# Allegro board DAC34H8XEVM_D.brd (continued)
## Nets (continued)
N27118781: C265.2 C268.1 L33.1 R23.1 R100.2 R107.1
N27125590: C274.2 C277.1 L38.1 R31.1 R101.2 R109.1
N27129848: C283.2 C286.1 L42.1 R39.1 R102.2 R111.1
N27288441: R79.2 U3.2(D4)
N27288443: C95.1 J14.2(D-) U3.16(USBDM)
N27288450: C92.1 C93.1 FB14.1 U3.20(VCC)
N27288471: R80.2 U3.9(D5)
N27288510: R81.2 U3.10(D6)
N27288614: C97.1 U3.17(3V3OUT)
N27288630: C96.1 J14.3(D+) U3.15(USBDP)
N27288689: R75.1 U4.8(A1) U9.2(1A)
N27288797: R75.2 U3.1(D0)
N27288876: R76.2 U3.5(D1)
N27289021: R77.2 U3.3(D2)
N27289053: R82.2 U3.6(D7)
N27299600: R78.1 U5.9(A2)
N27358249: R16.1 T1.4(SECONDARY_DOT) T8.6(PRIMARY_DOT)
N27358251: R13.2 R16.2
N27379986: R42.1 T4.4(SECONDARY_DOT) T11.6(PRIMARY_DOT)
N27396936: R4.1 T1.6(SECONDARY) T8.4(PRIMARY)
N27404153: R36.1 T4.6(SECONDARY) T11.4(PRIMARY)
N27685853: R7.2 R99.1
N27688076: R22.2 R100.1
N27690605: R30.2 R101.1
N27692844: R38.2 R102.1
N27760065: C76.1 C77.1 C78.1 C79.1 C80.1 C81.1 FB9.2 U2.26(VCC_OUT#26) U2.29(VCC_OUT#29) U2.32(VCC_OUT#32)
N27760104: C65.1 C66.1 FB5.2 U2.47(VCC_IN_PRI)
N27760106: C64.2 U2.38(REG_CAP2)
N27760178: C180.1 FB25.2 JP7.1
N27760241: C177.1 R95.1 U17.5(OUT)
N27760265: C53.1 J9.1(CENTER) R49.2
N27760429: C75.2 U2.4(REG_CAP1)
N27760435: JP4.3(PIN3) R51.2 R103.2
N27760437: C86.1 C87.1 FB12.2 U2.8(VCC_OUT#8)
N27760441: JP5.2(PIN2) U2.31(REF_SEL)
N27760496: C82.1 C83.1 FB10.2 U2.21(VCC_OUT#21)
N27760516: C73.1 C74.1 FB8.2 U2.1(VCC_IN_SEC)
N27760568: R61.2 R65.1 R116.1 R129.2 U2.9(U3P)
N27760578: C177.2 R166.2 R167.2 U2.3(SEC REF+)
N27760635: R164.2 R165.1 TP14.1(TP) U16.8(EN) U17.1(REF)
N27760767: R60.2 R64.1 R117.1 R130.1 U2.10(U3N)
N27760883: R55.2 U2.30(TESTOUTA)
N27760967: C52.2 R48.2
N27760969: JP6.2(PIN2) U2.12(P\W\R\D\W\N\)
N27760997: C67.1 C68.1 FB6.2 U2.5(VCC1_PLL)
N27761158: C88.1 C89.1 FB13.1 U2.18(VCC_OUT#18)
N27761194: D1.1(ANODE) R52.2
N27761235: R52.1 U2.37(PLL_LOCK)
N27761514: R54.2 U2.6(U4P)
N27761516: R58.2 U2.7(U4N)
N27761629: C63.2 U2.48(VBB)
N27761758: C84.1 C85.1 FB11.2 U2.11(VCC_OUT#11)
N27792689: C1.2 R122.2 R149.2
N27792693: C2.2 R123.2 R152.2
N27795123: C4.2 R125.2 R155.2
N27795145: C3.2 R124.2 R154.2
N27836250: J18.1 JP10.1(PIN1) TP12.1(TP)
N27836254: D2.1(ANODE) R143.1
N27959634: C165.1 FB31.1 L25.2 R148.2 U11.4(FB1)
N27964126: L25.1 U11.6(SW1)
N27965290: R148.1 R151.2 U11.5(DEF_1)
N27972790: C166.1 C167.1 FB30.1 L26.2 R150.2
N27972794: C166.2 R150.1 R153.2 U11.1(ADJ2)
N28017911: C162.1 U12.5(NR/FB)
N28017929: C145.1 C164.1 R147.1 U12.4(OUT)
N28017933: C163.1 R146.2 U12.1(EN) U12.2(IN)
N28058738: C133.1 C169.1 C234.1 FB31.3 R126.2 R145.2 R146.1 U13.1(IN) U13.3(EN)
N29123763: R9.1 T1.5(SECONDARY_CT)
N29143306: R12.1 T2.5(SECONDARY_CT)
N29165572: R14.1 T3.5(SECONDARY_CT)
N29179841: R18.1 T4.5(SECONDARY_CT)
N29448574: R36.2 R40.1
N29464199: R20.2 R24.1
N29945616: R133.2 U1.D12(PLLLF)
N30016149: C240.1 R126.1 U22.1(IN) U22.3(EN)
N30175128: C146.1 C244.1 C245.1 FB34.1 R128.2 R257.2 U13.5(OUT)
N30185572: C149.1 C246.1 C247.1 R127.1 R221.2 U22.5(OUT)
N30679143: C138.1 JP11.2 JP11.4 R134.1 R135.2 U20.5(NR/FB)
N30742942: JP11.1 R137.2
N30744213: JP11.3 R136.2
N30812023: R76.1 U4.9(A2) U9.12(4A)
N30837851: R85.1 U4.5(B1)
N30839067: R138.1 U4.4(B2)
N30879489: R139.1 U5.5(B1)
N30880109: R140.1 U5.4(B2)
N30892277: R84.1 U9.3(1Y)
N30900342: R74.2 R80.1 U9.5(2A)
N30908653: R86.1 U9.6(2Y)
N30910378: R79.1 R83.2 U9.13(4O\E\) U10.1(OE)
N30914286: R82.1 U9.8(3Y)
N30924628: JP13.2 R87.2 U10.2(A)
N30955591: R81.1 U10.4(Y)
N30963273: R73.2 R77.1 U5.8(A1)
N30997791: JP9.2 R84.2
N30998469: JP12.2 R86.2
N31553936: R87.1 U9.11(4Y)
N32018373: JP8.2 U9.9(3A)
N33970284: R221.1 R315.2 U22.4(NR/FB)
N33977043: R257.1 R316.2 U13.4(NR/FB)
N34116776: C116.1 U15.6(NR)
N34116835: R168.2 R170.1 U15.3(FB/SNS)
N34123238: FB35.1 R127.2 R128.1
N34173216: R105.2 T8.1(SECONDARY_DOT)
N34173251: R104.2 T8.3(SECONDARY)
N34173344: C254.2 C259.1 L30.1 R10.1 R99.2 R105.1
N34173621: R107.2 T9.1(SECONDARY_DOT)
N34173656: R106.2 T9.3(SECONDARY)
N34174309: R109.2 T10.1(SECONDARY_DOT)
N34174344: R108.2 T10.3(SECONDARY)
N34174546: R111.2 T11.1(SECONDARY_DOT)
N34174581: R110.2 T11.3(SECONDARY)
N34195362: R131.1 U6.19(S1)
N34195366: C100.2 R206.1 U6.3(IN)
N34195397: C54.2 R70.1 R206.2 R207.1
N34195475: C99.2 R207.2 U6.4(/IN)
N34209596: J20.1(CENTER) R122.1
N34209604: J21.1(CENTER) R123.1
N34210478: J22.1(CENTER) R124.1
N34210481: J23.1(CENTER) R125.1
N34222239: J10.1(CENTER) R121.1
N34226368: J11.1(CENTER) R120.1
N34231598: J12.1(CENTER) R129.1
N34231946: J15.1(CENTER) R130.2
N34233040: J19.1(CENTER) U2.14(S\Y\N\C\)
N34259421: C252.2 C256.1 L27.1 L28.2
N34259427: C256.2 C257.1 L29.1 L30.2
N34269055: C260.2 C264.1 L31.1 L32.2
N34269061: C264.2 C267.1 L33.2 L34.1
N34269953: C270.2 C273.1 L35.2 L36.1
N34269959: C273.2 C276.1 L37.1 L38.2
N34270526: C279.2 C282.1 L39.2 L40.1
N34270532: C282.2 C285.1 L41.1 L42.2
N34315833: F3.1 JP10.2(PIN2) Q3.1(D1) Q3.2(D2) Q3.5(D5) Q3.6(D6) Q3.8(D8) U21.5(VIN)
N34315835: C152.1 C153.1 F3.2 FB20.2 Q3.4(S4) Q3.7(S7)
N34320644: Q3.3(G3) U21.4(GATE)
N34334652: J13.177 R157.1
N34334661: J13.175 R156.1
N277617093: R95.2 U16.5(OUT)
N279448106: L26.1 U11.10(SW2)

Pads without a net: J13 5 6 7 8 9 10 11 12 13 14 15 16 17 18 19 20 21 22 23 24 25 26 27 28 30 32 34 36 37 38 39 40 41 42 43 44 45 46 47 48 49 50 51 52 53 54 55 56 57 58 59 60 61 62 63 64 169 171; J14 4; NOREF#3 1; NOREF#8 1; NOREF#22 1; NOREF#27 1; NOREF#28 1; NOREF#29 1; T1 2; T2 2; T3 2; T4 2; T8 2 5; T9 2 5; T10 2 5; T11 2 5; U2 13 27 28 33; U3 8 12 13 14 22 23 24 27 28; U6 9 10 12 21 22; U21 1 3

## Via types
v1: diameter 0.914, hole 0.254, TOP to BOTTOM, 4 vias
v2: diameter 0.508, hole 0.254, TOP to BOTTOM, 1708 vias
v3: diameter 0.762, hole 0.381, TOP to BOTTOM, 72 vias
v4: diameter 0.61, hole 0.33, TOP to BOTTOM, 9 vias
v5: diameter 0.61, hole 0.305, TOP to BOTTOM, 17 vias

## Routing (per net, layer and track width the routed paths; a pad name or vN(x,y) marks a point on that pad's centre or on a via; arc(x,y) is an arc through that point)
+1.2VCLK: length 46.8
  TOP w0.508: 76.05,25.15 75.92,25.15 75.92,24.54 C238.1
  TOP w0.762: 76.05,25.27 v2(76.68,24.64) ; 76.05,25.27 76.05,25.15 ; 76.05,25.27 76.05,25.4 C242.1 ; 76.05,25.27 75.92,25.15 ; 76.05,25.27 76.43,25.65 ; 76.05,25.27 v2(77.19,25.27) ; v2(76.68,24.64) v2(77.57,24.64) ; v2(76.68,24.64) 76.68,21.42 ; v2(76.68,24.64) 76.43,24.38 C238.1 76.07,22.96 C148.1 ; 77.32,26.92 TP19.1 76.43,28.45 v2(77.95,26.92) ; 77.32,26.92 v2(77.95,26.92) ; 77.32,26.92 v2(77.19,26.92) ; 76.68,21.42 FB35.2 ; 76.68,21.42 76.17,21.93 C148.1 ; FB35.2 77.57,21.3 ; FB35.2 v2(77.19,25.27) ; 76.43,26.04 76.43,25.65 ; 76.43,26.04 C242.1 ; 76.43,26.04 v2(76.43,26.29) 76.56,26.29 v2(77.19,26.92) ; 76.43,25.65 v2(76.43,25.53) ; C242.1 75.92,27.79 ; C148.1 76.17,23.24 v2(77.57,24.64) ; v2(77.57,24.64) 77.57,24.89 v2(77.95,25.27) ; v2(77.57,24.64) 77.57,21.3 ; 77.57,21.3 77.95,21.68 v2(77.95,25.27) ; v2(77.19,26.92) 77.19,26.52 ; v2(77.95,25.27) v2(77.95,26.04) v2(77.95,26.92) ; v2(77.19,25.27) v2(77.19,26.04)
  TOP w1.524: v2(77.19,26.04) 77.19,26.52 75.79,27.91 TP19.1
  BOTTOM w0.152: U1.C12 49.04,71.04 C38.1
  BOTTOM w0.508: v2(58.76,64.53) C40.1 v2(57.79,65.53)
+1.2VD: length 37.3
  TOP w0.305: C25.1 v2(40.61,60.43) ; C36.1 v2(39.57,60.05) ; C32.1 v2(39.55,59.28)
  TOP w0.508: 55.85,31.42 55.58,31.14 54.94,31.14 v2(54.71,31.37) C233.1
  TOP w1.016: 57.38,31.75 FB30.3 C134.1 55.85,31.24 v2(55.85,31.75) ; 57.38,31.75 56.74,32.38 ; 57.38,31.75 v2(55.85,31.75) ; 52.68,31.5 v2(51.92,30.73) ; 52.68,31.5 v2(51.92,31.5) ; 52.68,31.5 v2(52.81,31.5) ; v2(51.92,30.73) 51.03,30.73 TP15.1 50.65,32.38 v2(51.92,32.38) ; v2(51.92,30.73) v2(51.92,31.5) ; 56.74,32.38 57.76,32.38 58.5,31.65 ; 56.74,32.38 55.17,32.38 ; v2(52.81,31.5) v2(53.82,31.5) 54.58,31.5 v2(54.71,31.37) ; v2(52.81,31.5) v2(52.81,32.38) ; v2(55.85,31.75) 55.45,31.75 55.17,32.03 55.17,32.38 ; v2(52.81,32.38) v2(51.92,32.38) ; v2(52.81,32.38) 55.17,32.38 ; v2(51.92,32.38) v2(51.92,31.5)
  TOP w1.524: TP15.1 51.66,31.75 v2(51.92,31.5)
  L3_PWR w0.254: U1.D7 U1.E7
  L3_PWR w0.305: U1.F5 43.34,68.55 43.69,68.2 ; U1.E5 43.34,69.41 43.64,69.11
  BOTTOM w0.127: C26.1 43.41,68.64 U1.F5 ; C31.1 43.45,66.24 U1.J5
  BOTTOM w0.254: U1.D7 U1.E7
  BOTTOM w0.305: v2(46.28,60.93) C33.1 v2(46.69,60.53) C28.1 ; C29.1 v2(39.14,63.35) ; C27.1 v2(39.57,61.72)
  BOTTOM w0.508: v2(44.45,52.78) 44.45,53.66 C30.1 44.45,53.84 v2(44.45,54.71)
  vias: v2(57,30.73)
+1.2VDAC: length 36.8
  TOP w0.508: v2(66.9,23.62) v2(67.67,23.62) ; v2(66.9,23.62) 66.4,23.11 C243.1 ; v2(66.9,23.62) 66.9,23.16 ; v2(67.67,23.62) 68.05,23.24 ; v2(67.67,23.62) 67.92,23.62 v2(68.43,24.13) v2(68.43,23.24) ; v2(67.92,22.1) 67.51,22.5 66.4,22.5 ; v2(67.92,22.1) v2(67.16,22.1) ; v2(67.92,22.1) 67.92,22.61 ; v2(67.16,22.1) 66.52,22.1 66.4,22.22 ; v2(67.16,22.1) 66.78,21.72 C170.1 66.4,21.87 66.4,22.22 ; 66.4,22.22 66.4,22.5 ; FB34.2 68.69,19.41 67.77,19.41 66.98,20.19 ; C243.1 v2(66.9,22.86) ; C243.1 66.4,22.5 ; v2(66.9,22.86) 66.9,23.16 ; v2(66.9,22.86) v2(67.67,22.86) 67.92,22.61 ; v2(68.43,23.24) 67.92,22.73 67.92,22.61 ; v2(68.43,23.24) 68.05,23.24 ; 66.9,23.16 66.98,23.24 68.05,23.24
  TOP w1.016: v2(68.43,23.24) 68.43,20.92 ; 68.43,20.92 69.15,20.19 ; 68.43,20.92 67.92,21.42 v2(67.92,22.1) ; C170.1 66.65,21.62 C147.1 ; 67.74,20.19 67.16,20.78 v2(67.16,22.1)
  TOP w1.27: C147.1 69.15,20.19 FB34.2
  TOP w1.524: 68.11,23.81 66.78,25.15 TP18.1 66.01,24.51 v2(66.9,23.62)
  BOTTOM w0.127: C20.1 46.46,69.44 U1.E9 ; C19.1 46.54,64.56 U1.L9 ; U1.K9 46.46,65.44 C13.1 ; C18.1 46.54,70.31 U1.D9 ; C23.1 47.25,68.64 U1.F10
  BOTTOM w0.152: U1.G10 47.25,67.84 C21.1 ; C14.1 47.25,67.04 U1.H10
  BOTTOM w0.305: v2(50.93,61.59) 50.9,61.62 C15.1 ; v2(50.04,61.26) 49.76,61.54 C16.1
  BOTTOM w0.508: v2(49.59,57.37) C24.1 v2(50.52,56.36)
+3.3V_LOGIC: length 15.7
  BOTTOM w0.254: U5.6 102.47,119.88 v2(102.11,120.24) ; v2(95.45,120.27) 95.71,120.01 U4.6
  BOTTOM w0.508: C139.1 v2(95.58,120.95) ; C141.1 v2(102.21,120.95)
  BOTTOM w1.016: 82.88,126.37 v2(83.9,127.38) ; 82.88,126.37 83.79,126.37 v2(83.9,126.26) ; 82.88,126.37 FB24.2 ; 82.88,126.37 82.88,126.26 v2(83.9,125.25) ; v2(82.93,124.28) 82.64,124.57 82.64,124.96 ; v2(83.82,124.28) 83.15,124.96 82.64,124.96 ; 82.64,124.96 v2(81.99,124.31) ; 82.64,124.96 FB24.2 ; 82.64,127.8 82.64,128.03 v2(82.98,128.37) ; 82.64,127.8 v2(82.04,128.4) ; 82.64,127.8 83.3,127.8 v2(83.87,128.37) ; 82.64,127.8 FB24.2
+3.3VA: length 22.1
  TOP w0.508: v2(65.38,4.57) R147.2 v2(66.27,5.33) ; v2(55.98,8.26) 55.98,7.87 56.36,7.49 ; 56.36,7.49 56.74,7.87 v2(56.74,8.26) ; 56.36,7.49 R145.1
  L6_PWR w0.127: U1.E11 U1.D10
  BOTTOM w0.102: U1.L10 47.34,64.55 C7.1
  BOTTOM w0.127: U1.D10 47.34,70.33 C8.1
  BOTTOM w0.152: C12.1 48.2,68.64 U1.F11 ; U1.J11 48.25,66.24 C10.1 ; C9.1 48.2,69.44 U1.E11
  BOTTOM w0.305: C6.1 v2(51.54,67.84) ; C11.1 v2(51.54,67.03) ; C5.1 v2(51.56,64.64)
  BOTTOM w0.508: v2(50.71,52.39) C22.1 v2(49.76,53.39)
  BOTTOM w1.016: 59.44,68.55 59.92,68.55 v2(60.05,68.68) ; 59.44,68.55 v2(60.07,67.92) ; 59.44,68.55 FB1.2 ; FB22.1 48.64,42.86 48.64,41.97 ; FB22.1 48.32,44.7 ; FB22.1 49.4,43.18 ; v2(49.53,42.55) 49.4,42.67 49.4,43.18 ; 48.32,44.7 v2(49.53,44.7) ; 48.32,44.7 48.32,44.77 ; FB1.2 59.41,67.95 v2(59.44,67.92) ; FB1.2 58.88,68.55 v2(58.78,68.66) ; FB1.2 v2(58.78,67.92) ; v2(48.64,41.28) 48.64,41.97 ; 48.64,41.97 49.53,41.97 v2(49.53,41.78) ; v2(48.64,45.09) 48.32,44.77 ; 48.32,44.77 48.07,44.77 v2(47.75,45.09) ; v2(49.53,43.31) 49.4,43.18 ; 49.4,43.18 49.4,43.94 v2(49.53,44.07)
  vias: v2(47.75,41.28)
+3.3VCLK: length 77.3
  TOP w0.305: U2.15 v2(61.21,108.68) 61.21,108.32 v2(60.93,108.05) C127.1 ; U6.1 v2(49.59,96.8) ; 23.04,105.16 23.04,105 22.94,104.9 21.54,104.9 21.37,105.07 U15.1 ; v2(49.65,97.99) 49.34,97.99 U6.2 ; v2(48.23,99.55) 48.23,99.31 48.23,99.31 48.23,99 U6.5 ; U15.2 22.55,105.72 23.04,105.23
  TOP w0.508: C179.1 v2(61.67,136.02) ; R63.1 v2(63.07,104.53) ; 24.1,105.16 R170.2 23.04,105.16 23.04,105.23 ; 24.1,105.16 24.1,105.74 24.46,105.74 24.69,105.51 ; 24.1,105.16 24.33,105.16 C215.1 ; R62.1 v2(66.12,104.54) ; v2(28.02,104.01) 28.02,103.63 ; v2(28.02,104.01) 28.4,104.39 ; v2(28.02,104.01) v2(25.73,104.01) ; 28.02,103.63 v2(28.4,103.25) ; 28.02,103.63 27.38,103.63 ; 24.85,104.89 24.69,104.89 24.57,105 23.04,105 ; 24.85,104.89 26,104.89 v2(26.11,104.78) ; 24.85,104.89 24.85,104.72 25.57,104.01 v2(25.73,104.01) ; 24.85,104.89 v2(25.73,104.01) ; 26.11,105.11 27.96,105.11 28.02,105.16 ; 26.11,105.11 v2(26.11,104.78) ; 26.11,105.11 C118.1 ; 26.11,104.39 v2(25.73,104.01) ; 26.11,104.39 28.4,104.39 ; 26.11,104.39 v2(26.11,104.78) ; v2(25.73,104.01) 25.73,103.89 25.98,103.63 25.98,103.56 ; v2(25.73,104.01) 25.73,105.13 C118.1 ; R68.1 v2(61.93,104.54) ; 28.4,104.39 v2(28.4,104.78) ; 28.4,104.39 v2(28.4,103.25) ; v2(26.11,104.78) v2(26.87,104.78) v2(27.64,104.78) v2(28.4,104.78) ; C118.1 26.85,105.51 v2(26.87,105.54) 27.41,105.54 ; C118.1 26.34,105.74 27.41,105.74 27.41,105.54 ; 28.02,105.16 v2(28.4,104.78) ; 28.02,105.16 v2(27.64,105.54) 27.41,105.54 ; v2(28.4,103.25) 27.38,103.25 ; v2(28.4,103.25) 28.4,103.12 27.31,102.04 26.64,102.04 25.98,102.69 25.98,103.56 ; 27.38,103.25 TP17.1 26.06,103.56 ; 27.38,103.25 27.38,103.63 ; R60.1 v2(53.21,106.43) ; 26.06,103.56 26.14,103.63 27.38,103.63 ; 26.06,103.56 25.98,103.56 ; R51.1 v2(61.52,132.92) ; R166.1 52.92,116.35 v2(52.91,116.33) ; v2(58.88,104.51) 58.88,104.51 R69.1 ; R53.1 52.34,114.72 v2(52.34,115.28) ; R57.1 v2(52.86,111.63) ; R47.1 v2(67.77,130.05) ; R91.1 v2(42.52,94.41) ; R61.1 v2(53.21,110.49) ; R89.1 v2(44.67,92.26)
  TOP w1.016: C215.1 24.69,105.51 C118.1
  BOTTOM w0.305: C104.1 50.36,97.99 v2(49.65,97.99)
  BOTTOM w0.508: FB12.1 55.88,111.73 v2(55.75,111.86) ; FB11.1 v2(56.29,109.6) ; v2(56.03,115.82) 56.03,115.57 FB8.1 ; FB13.2 v2(62.83,105.91) ; FB7.1 v2(69.7,116.28) ; FB4.1 v2(65.33,120.14) ; FB3.1 v2(61.98,120.19) ; v2(55.7,113.82) 55.91,113.61 FB6.1 ; C128.1 v2(59.72,107.65) ; FB5.1 v2(58.97,120.23) ; v2(70.28,109.88) FB9.1 v2(69.75,109.32) ; C103.1 v2(48.15,100.19) ; v2(50.18,96.87) C102.1 ; FB15.2 v2(47.35,92.7) ; FB10.1 v2(65.41,106.45)
  BOTTOM w1.016: v2(76.07,124.33) 76.49,124.75 77.38,124.75 ; 77.38,127.93 v2(77.85,128.4) ; 77.38,127.93 77.38,127.98 v2(76.96,128.4) ; 77.38,127.93 76.54,127.93 v2(76.07,128.4) ; 77.38,127.93 FB24.1 ; v2(77.85,124.33) 77.43,124.75 77.38,124.75 ; FB24.1 77.38,124.75 ; FB24.1 77.17,126.37 ; 77.38,124.75 v2(76.96,124.33) ; v2(76.07,126.37) 77.17,126.37 ; 77.17,126.37 77.17,126.42 v2(76.07,127.51)
  vias: v2(76.07,125.35)
+3.3VD: length 14.4
  L3_PWR w0.305: 43.56,70.48 43.34,70.26 U1.D5
  L6_PWR w0.305: U1.L5 43.34,64.59 43.61,64.31
  BOTTOM w0.127: U1.L6 44.15,64.63 C43.1 ; C45.1 43.34,70.29 U1.D5 ; C44.1 43.34,64.56 U1.L5 ; U1.H5 43.45,67.04 C41.1 ; U1.G5 43.43,67.84 C42.1 ; C46.1 44.14,70.3 U1.D6
  BOTTOM w1.016: v2(42.55,45.21) 43.05,44.7 ; 43.05,44.7 43.05,43.38 42.88,43.38 ; 43.05,44.7 42.16,44.7 v2(41.91,44.96) ; 43.05,44.7 v2(43.56,45.21) ; v2(41.91,41.53) 42.47,42.09 42.88,42.09 ; 42.88,42.09 42.88,43.38 ; 42.88,42.09 42.88,41.61 v2(42.55,41.28) ; 42.88,42.09 v2(43.69,41.28) ; 42.88,43.38 41.99,43.38 ; 42.88,43.38 v2(41.91,42.42) ; 41.99,43.38 v2(41.91,43.31) 42.04,43.18 FB22.2 ; 41.99,43.38 41.99,43.99 v2(41.91,44.07)
+5V_USB: length 29.7
  TOP w0.508: J14.1 v2(113.67,118.14) 113.67,118.08 112.95,117.37 112.95,113.79 114.73,112.01 114.73,107.7 v2(116.28,106.15) 116.28,104.93 v2(116.33,104.88)
  BOTTOM w0.508: FB14.2 111.53,115.09 C91.1 112.95,118.14 v2(113.67,118.14) ; v2(116.28,106.15) U20.2 112.78,106.15 C136.1 C137.1 U20.1 v2(116.33,104.88)
GNDA: length 257.6
  TOP w0.254: v2(60.81,115.04) 60.66,115.18 U2.2 ; v2(71.22,6.48) U13.2 v2(69.82,6.48) ; U22.2 v2(79.22,6.35) ; C78.2 v2(69.65,112.29)
  TOP w0.305: C69.2 v2(69.65,115.34) ; R98.2 v2(52.93,70.54) ; U6.13 v2(44.2,96.33) ; C70.2 v2(69.65,114.58) ; U6.8 46.86,97.66 v4(46.88,97.66) ; C57.2 64.8,119.46 v2(64.67,119.58) ; R94.2 v2(52.83,66.75) ; C73.2 v2(56.68,116.09) ; v4(47.96,96.58) 47.96,96.57 U6.23 ; C127.2 v2(60.93,106.53) ; U6.18 46.3,94.25 46.74,94.69 46.74,95.36 v4(46.88,95.51) 47.8,94.59 U6.20 ; v2(20.13,106.75) 20.41,107.02 U15.4 21.37,107.02 v2(21.67,107.31) ; v2(40.56,59.74) 40.64,59.82 C25.2 ; v2(66.5,116.28) 66.48,116.27 U2.36 ; v2(56.29,112.39) 56.46,112.39 C86.2 ; v2(69.65,113.67) 69.64,113.67 C77.2 ; C58.2 62.39,119.29 v2(62.66,119.56) ; C56.2 63.22,119.51 v2(63.3,119.58) ; R33.2 v2(52.93,64.34) ; R41.2 v2(52.88,64.92) ; v2(44.27,98.11) 44.89,97.52 45.8,96.6 v4(45.8,96.58) 44.88,97.5 U6.11 ; v2(62.2,16.13) v2(62.2,16.89) U12.6 v2(62.2,17.65) ; C32.2 v2(38.18,59.28) ; U11.11 U11.8 v2(57.51,20.45) ; v2(69.65,110.64) 69.63,110.62 C76.2 ; C65.2 59.6,119.45 v2(59.77,119.61) ; U6.24 49.23,96 v2(49.86,95.38) ; R35.2 v2(52.07,62.51) ; v2(56.29,114.27) 56.51,114.05 C67.2 ; R112.2 v2(52.1,72.36) ; C82.2 v2(64.08,106.96) ; v5(62.45,114.46) 62.71,114.71 U2.43 ; R96.2 v2(52.83,69.95) ; C84.2 56.68,110.55 v2(56.41,110.82) ; C88.2 v2(62.15,106.68) ; R97.2 v2(52.83,68.12) ; C36.2 v2(38.13,60.05) ; U6.7 v2(45.71,99.52)
  TOP w0.381: v2(48.36,21.21) U21.2 v2(48.36,19.18)
  TOP w0.508: C238.2 v2(73.89,24.38) ; v2(6.96,107.82) C143.2 v2(7.85,107.04) ; v2(75.79,62.61) TP33.1 v2(77.11,62.61) ; C258.2 v2(63.75,47.24) ; R316.1 v2(73.81,4.95) ; C134.2 56.24,28.83 56.74,28.83 ; C134.2 56.16,28.96 56.49,29.29 58.06,29.29 FB30.2 ; C134.2 v2(55.22,28.96) ; C164.2 v2(62.08,5.33) ; C161.2 v2(48.11,25.65) ; v2(77.09,93.22) TP31.1 v2(75.79,93.22) ; R50.2 v2(67.77,129.03) ; C170.2 v2(64.36,21.72) ; R21.1 v2(75.97,58.04) ; C182.2 v2(51.05,133.96) ; R39.2 v2(75.97,89.66) ; C251.1 v2(63.75,44.2) ; C242.2 v2(74.4,25.53) ; v2(85.47,130.3) 85.51,130.26 SW1.1 v2(85.51,126.45) ; v2(13.03,107.04) C144.2 v2(13.92,107.8) ; v2(46.25,91.65) C90.2 ; v2(97.03,72.87) T3.1 v2(98.22,73.79) ; v2(97.03,92.76) T4.3 v2(98.27,91.82) ; C284.2 v2(63.75,90.68) ; R55.1 v2(72.19,112.96) ; R56.2 51.32,114.73 v2(51.32,115.34) ; C257.2 v2(69.85,47.24) ; FB30.2 v2(59.41,29.21) ; FB30.2 57.76,29.21 57.38,28.83 56.74,28.83 ; C63.1 v2(57.86,120.19) ; R71.2 v2(61.93,102.46) ; v2(58.88,102.48) 58.88,102.99 58.88,103 R72.2 ; C286.2 v2(71.88,90.68) ; R153.1 v2(53.44,30.23) ; C165.2 v2(55.47,17.14) ; C266.2 v2(63.75,60.07) ; v2(77.11,72.26) TP28.1 v2(75.79,72.26) ; v2(75.79,54.48) TP34.1 v2(77.11,54.48) ; C253.1 v2(71.88,44.2) ; R131.2 v2(50.06,92.72) ; J14.5 v2(113.49,121.34) ; C279.1 69.85,87.63 ; D2.2 v2(40.87,29.21) ; C149.2 v2(77.57,9.53) ; v2(62.2,12.07) U12.3 v2(62.2,9.02) ; C234.2 v2(54.97,7.11) ; R6.1 v2(75.95,45.21) ; C268.2 v2(71.88,60.07) ; v2(85.51,125.18) SW1.2 85.51,121.45 v2(85.47,121.41) ; C261.1 v2(63.75,57.02) ; SW2.1 v2(106.74,126.73) ; R151.1 v2(55.47,18.29) ; v2(106.74,125.26) SW2.2 v2(106.74,121.53) ; v2(22.68,108.2) R168.1 v2(23.19,108.71) ; C116.2 v2(16.21,107.98) ; C252.1 v2(69.85,44.2) ; v2(52.68,7.11) FB31.2 v2(50.14,7.11) ; v2(75.79,41.66) TP29.1 v2(77.11,41.66) ; R29.1 v2(75.97,75.82) ; C275.2 v2(63.75,77.85) ; R64.2 v2(52.2,106.43) ; R65.2 52.2,110.49 v2(52.17,110.52) ; v2(51.32,111.06) 51.32,111.61 R59.2 ; C259.2 v2(71.88,47.24) ; C269.1 v2(63.75,74.8) ; C178.2 v2(52.07,133.91) ; v2(98.32,60.96) T2.3 v2(97.16,61.87) ; v2(50.85,119.79) C75.1 v2(49.99,119.02) ; C169.2 v2(68.55,7.37) ; v2(20.4,101.09) C135.2 v2(19.63,101.98) ; v2(47.4,123.55) U17.4 v2(46.09,122.49) ; v2(75.79,49.78) TP30.1 v2(77.11,49.78) ; C215.2 v2(24.59,108.2) ; R31.2 v2(75.97,76.84) ; R167.1 v2(52.96,117.36) ; C250.2 v2(99.85,109.73) ; 56.74,28.83 v2(56.74,28.19) ; J14.8 v2(113.67,115.29) ; R10.2 v2(75.97,46.23) ; R315.1 v2(81.94,4.67) ; R66.2 v2(66.12,102.48) ; C245.2 v2(69.06,12.45) ; v2(19.25,103.25) 19.28,103.23 C117.2 v2(19.89,102.62) ; C262.1 v2(71.88,57.02) ; R90.2 v2(43.93,90.84) ; R49.1 v2(67.77,133.1) ; C118.2 v2(26.11,107.7) ; C278.1 v2(63.75,87.63) ; C233.2 v2(54.71,29.21) ; v2(77.11,80.39) TP27.1 v2(75.79,80.39) ; v2(98.32,43.18) T1.1 v2(97.16,42.24) ; C111.2 v2(49.63,24.89) ; C276.2 v2(69.85,77.85) ; C162.2 v2(66.78,11.56) ; C267.2 v2(69.85,60.07) ; R67.2 v2(63.07,102.51) ; R103.1 v2(61.67,133.93) ; C247.2 v2(78.59,12.19) ; R23.2 v2(75.95,59.05) ; C148.2 v2(73.38,22.86) ; C280.1 v2(71.88,87.63) ; C147.2 v2(63.86,20.19) ; D1.2 v2(68.63,123.22) ; C270.1 v2(69.85,74.8) ; C244.2 v2(68.55,11.3) ; C180.2 v2(55.14,137.9) ; C145.2 v2(63.6,4.57) ; C277.2 v2(71.88,77.85) ; C237.2 v2(51.79,24.13) ; v2(75.77,85.09) TP32.1 v2(77.11,85.09) ; C240.2 v2(76.68,7.37) ; C181.2 v2(56.15,134.2) ; R164.1 v2(49.02,135.99) ; J14.9 v2(122.31,115.29) ; 90.81,116.31 v2(91.36,116.31) ; J14.7 v2(113.67,124.19) ; C146.2 v2(68.05,9.78) ; C246.2 v2(78.08,11.05) ; R92.2 v2(41.08,93.69) ; v2(64.87,22.86) C243.2 ; C179.2 v2(61.65,135) ; C112.2 v2(50.77,24.13) ; v2(41.9,95.99) C101.2 ; C167.2 v2(50.77,27.05) ; C133.2 v2(53.57,8.13) ; C285.2 v2(69.85,90.68) ; C64.1 v2(66.62,123.39) ; R37.1 v2(75.97,88.65) ; C163.2 v2(60.17,3.3) ; J14.6 v2(122.31,124.19) ; C260.1 v2(69.85,57.02) ; C50.2 v2(109.22,119.53) ; C271.1 v2(71.88,74.8)
  L2_GND w0.305: 96.27,44.02 96.27,43.69 96.01,43.43
  BOTTOM w0.127: U1.M9 46.54,63.91 C19.2 ; C46.2 44.14,70.92 U1.C6 ; C14.2 46.63,67.04 U1.H9 ; U1.G9 46.63,67.84 C21.2 ; U1.J6 44.08,66.24 C31.2 ; U1.K8 45.84,65.44 C13.2 ; U1.E8 45.84,69.44 C20.2 ; C43.2 44.14,63.93 U1.M6 ; U1.C9 46.54,70.96 C18.2 ; C44.2 43.34,63.91 U1.M5 ; U1.J9 46.63,66.24 C17.2 ; U1.F9 46.63,68.64 C23.2 ; C8.2 47.34,70.95 U1.C10 ; U1.H6 44.08,67.04 C41.2 ; U1.G6 44.05,67.84 C42.2 ; C26.2 44.06,68.64 U1.F6
  BOTTOM w0.152: J13.113 7.52,70.53 7.52,70.51 ; C45.2 43.34,70.94 U1.C5 ; J13.120 11.2,69.03 11.2,69.04 ; C5.2 50.57,64.64 U1.L14 ; C12.2 48.82,68.64 U1.F12 ; 13.26,62.51 13.29,62.54 J13.126 ; J13.143 7.29,58.04 7.26,58.06 ; 6.86,78.03 6.86,78.04 J13.83 ; C38.2 49.66,71.04 U1.C13 ; J13.155 7.25,55.03 7.24,55.04 ; 13.06,73.48 13.11,73.54 J13.102 ; J13.84 13.37,78.04 13.36,78.03 ; 7.26,62.48 7.32,62.54 J13.125 ; J13.156 12.71,55.03 12.65,55.09 ; J13.101 6.5,73.54 6.5,73.58 ; J13.138 12.73,59.54 12.52,59.33 ; J13.95 6.55,75.04 6.55,75.01 ; C10.2 48.88,66.24 U1.J12 ; U1.M10 47.35,63.84 C7.2 ; C6.2 U1.G14 ; 12.8,50.57 12.84,50.53 J13.174 ; 12.67,53.19 13.02,53.53 J13.162 ; 12.04,56.54 12.04,56.54 J13.150 ; 12.83,79.58 12.87,79.54 J13.78 ; U1.P13 49.75,62.24 C16.2 ; C11.2 U1.H14 ; J13.96 13.34,75.04 13.34,75.03 ; C9.2 48.83,69.44 U1.E12 ; 12.73,72.39 12.75,72.36 ; 12.75,72.36 12.78,72.34 12.78,70.74 12.98,70.53 J13.114 ; 12.75,72.36 12.75,72.19 12.9,72.03 J13.108 ; 7.19,61.11 7.26,61.04 J13.131 ; J13.137 7.24,59.54 7.21,59.51 ; 12.83,60.96 12.91,61.04 J13.132 ; 7.49,72.06 7.49,72.03 J13.107 ; 12.8,81.03 12.82,81.04 J13.72 ; 7.37,53.49 7.39,53.52 7.57,53.52 7.58,53.53 J13.161 ; 6.35,76.45 6.35,76.54 J13.89 ; J13.168 13.37,52.03 13.34,51.99 ; J13.77 7.44,79.54 7.44,79.53 ; 7.39,81.03 7.39,81.04 J13.71 ; J13.144 12.11,58.04 12.09,58.01 ; J13.149 7.28,56.54 7.24,56.49 ; 13.36,76.53 13.37,76.54 J13.90
  BOTTOM w0.254: v2(95.4,117.48) 95.71,117.78 U4.2 ; v2(103.2,117.42) 102.87,117.76 U5.1 ; U5.3 v2(101.67,118.04) ; U4.3 v2(94.91,117.97) ; U5.2 v2(102.47,117.33)
  BOTTOM w0.305: U3.26 v2(97.1,106.53) ; C54.1 51.66,98.34 v2(51.66,98.16) ; U3.25 v2(97.75,106.54) ; C33.2 46.28,59.66 v2(46.43,59.51) ; U3.21 v2(100.35,106.58) ; C28.2 v2(47.09,59.49) ; C27.2 v2(38.23,61.72) ; C29.2 v2(37.74,63.35) ; U3.18 v2(102.3,106.57)
  BOTTOM w0.381: v2(99.06,128.09) 99.09,128.09 99.42,128.43 U9.1 ; U3.7 v2(99.7,111.08) ; U9.10 v2(102.02,124.88) ; U9.4 v2(101.37,127.97) ; U9.7 v2(103.32,127.93)
  BOTTOM w0.508: C71.2 65.51,112.9 v2(65.1,113.31) ; v5(61.43,112.42) 61.18,112.17 v2(60.81,112.17) C87.2 ; v2(52.32,124.97) U16.4 v2(51.59,124.1) ; v2(59.87,106.48) 60.27,106.07 C128.2 60.48,106.07 v2(60.93,106.53) ; C68.2 v2(60.81,113.72) ; v2(61.33,64.55) C40.2 v2(62.28,65.53) ; R45.2 v2(48.67,54.38) ; C153.2 v2(40.74,26.8) ; C62.2 42.41,97.03 v2(42.98,97.03) ; v2(116.31,107.42) U20.3 113.69,107.42 113.21,106.93 112.55,106.93 R134.2 v2(112.52,107.44) ; v5(62.45,111.41) 62.69,111.17 C89.2 ; v2(112.17,112.5) C93.2 v2(111.14,111.49) ; C80.2 65.68,111.53 v2(65.1,112.12) ; v2(70.51,118.08) 70.49,118.06 C72.2 ; C136.2 v2(111.02,105.89) ; C22.2 v2(49.76,48.84) ; v2(65.13,110.79) 65.46,110.46 C79.2 C81.2 ; v2(60.81,115.04) 60.83,115.01 v2(60.83,114.58) ; v2(60.81,115.04) 60.83,115.06 C66.2 ; v2(60.81,115.04) 60.76,114.99 C74.2 ; C94.2 v2(97.61,120.95) ; v2(62.23,115.11) 62.13,115.21 C61.2 ; R18.2 v2(88.75,88.24) ; C59.2 63.65,115.44 v2(63.65,115.09) ; C85.2 v2(60.74,110.72) v5(61.43,111.41) ; C92.2 v2(110.11,110.77) ; C98.2 v2(92.96,128.37) ; C34.2 v2(53.04,77.11) ; C104.2 v2(52.09,97.2) ; C137.2 v2(111,104.88) ; v2(47.96,53.75) C30.2 v2(46.93,52.74) ; v2(65.07,115.06) 65.53,115.52 C60.2 ; C35.2 v2(52.48,76.58) ; C154.2 v2(46.1,22.1) C155.2 v2(46.58,21.59) ; v2(51.52,54.8) C24.2 v2(50.52,53.77) ; C91.2 v2(110.01,116.71) ; C83.2 64.21,111.14 v5(64.48,111.41) ; C95.2 v2(109.98,118.75) ; C152.2 v2(38.33,29.46) ; C96.2 v2(109.96,120.02) ; U10.3 v2(94.19,124.59) ; C97.2 v2(98.68,116.51) ; C141.2 v2(101.19,120.93) ; C102.2 v2(51.28,95.17) ; R14.2 v2(88.85,75.29) ; R12.2 v2(88.9,57.43) ; C140.2 v2(104.32,120.93) ; R9.2 v2(89.1,44.73) ; C139.2 v2(94.56,120.95) ; C142.2 v2(95.86,124.05) ; C103.2 v2(46.74,100.89) ; C47.2 v2(87.17,125.3)
  vias: v2(1.02,99.7) v2(1.02,95.89) v2(1.02,92.08) v2(1.02,88.27) v2(1.02,84.45) v2(1.02,80.64) v2(1.02,76.84) v2(1.02,73.03) v2(1.02,69.22) v2(1.02,65.41) v2(1.02,61.59) v2(1.02,57.79) v2(1.02,53.98) v2(1.02,50.16) v2(1.02,46.36) v2(1.09,102.18) v2(5.72,111.12) v2(5.72,107.31) v2(7.11,38.23) v2(7.87,109.86) v2(8.76,66.04) v2(10.16,107.95) v2(10.77,105.56) v2(10.77,101.35) v2(10.77,46.81) v2(10.8,104.65) v2(10.8,103.89) v2(10.8,100.38) v2(10.8,99.38) v2(10.8,98.5) v2(10.8,94.03) v2(10.8,93.03) v2(10.8,92.08) v2(10.8,91.01) v2(10.8,88.7) v2(10.8,87.76) v2(10.8,86.84) v2(10.8,85.6) v2(10.8,84.65) v2(10.8,83.74) v2(10.8,81.15) v2(10.8,78.87) v2(10.8,77.34) v2(10.8,75.06) v2(10.8,73.53) v2(10.8,72.01) v2(10.8,67.75) v2(10.8,66.83) v2(10.8,65.56) v2(10.8,64.64) v2(10.8,61.42) v2(10.8,60.07) v2(10.8,57.4) v2(10.8,54.99) v2(10.8,54.1) v2(10.8,53.09) v2(10.8,52.07) v2(10.8,51.18) v2(10.8,48.69) v2(10.8,47.75) v2(10.8,37.47) v2(11.18,89.94) v2(12.19,47.24) v2(12.42,85.8) v2(12.7,114.94) v2(12.7,87.63) v2(13.46,42.93) v2(13.97,47.12) v2(14.61,46.36) v2(14.61,37.47) v2(14.68,87.68) v2(15.24,110.49) v2(15.6,101.83) v2(15.75,46.99) v2(15.82,85.73) v2(16.13,89.38) v2(16.64,42.93) v2(16.89,45.97) v2(17.78,114.94) v2(17.78,111.76) v2(17.78,97.79) v2(17.78,92.71) v2(18.06,89.43) v2(18.42,37.47) v2(19.13,106.75) v2(19.13,105.34) v2(19.35,90.83) v2(19.63,106.05) v2(19.91,88.39) v2(20.13,105.34) v2(20.32,110.49) v2(20.96,92.41) v2(21.03,98.47) v2(21.01,89.46) v2(22.23,114.94) v2(22.17,103.25) v2(22.23,37.47) v2(22.3,93.83) v2(22.86,97.79) v2(22.78,90.86) v2(23.06,88.57) v2(23.95,94.97) v2(23.98,92.05) v2(24.94,90.4) v2(25.25,93.8) v2(25.25,88.24) v2(25.55,96.57) v2(26.04,114.94) v2(26.04,37.47) v2(26.72,95.28) v2(26.7,92.18) v2(26.82,89.84) v2(27.2,98.2) v2(27.31,88.34) v2(27.94,110.49) v2(28.65,94.16) v2(28.65,91.64) v2(28.68,97.21) v2(28.96,40.39) v2(29.31,99.24) v2(29.62,88.27) v2(29.85,139.06) v2(29.85,134.62) v2(29.85,130.81) v2(29.85,127) v2(29.85,123.19) v2(29.85,119.38) v2(29.85,114.94) v2(29.85,37.47) v2(29.85,34.29) v2(29.85,30.48) v2(29.85,26.67) v2(29.85,22.86) v2(29.85,18.41) v2(29.85,13.34) v2(29.85,10.16) v2(29.85,6.35) v2(29.85,2.54) v2(30.3,95.76) v2(30.35,93.32) v2(30.48,113.03) v2(30.48,105.41) v2(30.78,44.27) v2(31.04,97.51) v2(31.6,99.21) v2(31.65,88.34) v2(32.16,95.12) v2(33.02,130.81) v2(33.02,120.65) v2(33.05,87.63) v2(33.02,16.51) v2(33.02,11.43) v2(33.35,96.93) v2(33.91,20.7) v2(34.11,44.2) v2(34.29,0.64) v2(34.44,97.54) v2(34.93,139.06) v2(35.1,87.4) v2(35.56,105.41) v2(35.56,41.91) v2(35.56,36.83) v2(35.56,31.75) v2(35.56,6.35) v2(36.25,96.88) v2(36.53,86.03) v2(36.83,134.62) v2(36.83,2.87) v2(37.26,89.43) v2(37.44,97.64) v2(37.39,87.43) v2(37.62,117.88) v2(37.69,116.03) v2(37.69,110.26) v2(37.85,125.63) v2(37.85,123.9) v2(37.82,108.41) v2(37.92,102.77) v2(38.05,84.4) v2(38.1,120.65) v2(38.1,113.03) v2(38.1,95.1) v2(38.1,44.45) v2(38.1,39.37) v2(38.1,34.29) v2(38.2,100.89) v2(38.38,104.75) v2(38.43,90.83) v2(38.46,47.09) v2(38.73,139.06) v2(38.73,98.04) v2(38.73,6.35) v2(38.73,0.64) v2(38.91,99.16) v2(38.96,88.47) v2(38.94,86.39) v2(38.96,26.67) v2(39.04,116.15) v2(39.24,122.68) v2(39.27,117.73) v2(39.29,110.64) v2(39.37,89.66) v2(39.45,108.64) v2(39.47,82.96) v2(39.62,130.63) v2(39.6,124.69) v2(39.62,106.78) v2(39.7,129.24) v2(39.7,126.92) v2(39.75,96.52) v2(40.11,101.22) v2(40.13,87.38) v2(40.51,103.05) v2(40.67,107.82) v2(40.64,36.83) v2(40.72,100.03) v2(40.77,81.66) v2(40.84,121.08) v2(40.89,115.57) v2(40.89,88.39) v2(40.89,85.34) v2(41,110.49) v2(40.97,90.78) v2(41.15,122.94) v2(41.25,127.48) v2(41.25,92.25) v2(41.33,125.04) v2(41.33,117.3) v2(41.38,130.73) v2(41.4,129.69) v2(41.43,105.74) v2(41.43,98.27) v2(41.81,113.77) v2(41.81,26.37) v2(42.01,80.42) v2(42.29,83.49) v2(42.42,104.14) v2(42.55,139.06) v2(42.49,101.73) v2(42.62,119.33) v2(42.57,107.29) v2(42.65,85.42) v2(42.72,123.55) v2(42.67,89.66) v2(42.67,87.45) v2(42.85,121.26) v2(42.8,110.49) v2(42.95,112.57) v2(43.1,116.41) v2(43.13,99.97) v2(43.08,90.83) v2(43.18,52.07) v2(43.18,46.99) v2(43.18,3.81) v2(43.18,0.64) v2(43.36,79.38) v2(43.64,25.22) v2(43.69,84.33) v2(43.84,81.86) v2(43.92,105.74) v2(44.15,103.48) v2(44.32,111.51) v2(44.27,108.56) v2(44.42,117.53) v2(44.45,81.1) v2(44.45,23.11) v2(44.5,121.82) v2(44.48,115.04) v2(44.63,83.39) v2(44.68,119.41) v2(44.81,104.11) v2(44.86,101.68) v2(44.78,84.61) v2(45.29,113.39) v2(45.39,80.26) v2(45.72,128.27) v2(45.72,36.83) v2(45.72,31.75) v2(45.85,110.54) v2(45.85,2.97) v2(45.95,29.21) v2(46.1,120.17) v2(46.15,115.82) v2(46.2,108.15) v2(46.36,139.06) v2(46.46,117.63) v2(46.43,105.71) v2(46.41,103.25) v2(46.53,20.02) v2(46.74,82.14) v2(46.81,113.94) v2(46.84,83.77) v2(46.91,111.68) v2(47.12,80.9) v2(47.35,106.98) v2(47.8,118.47) v2(47.78,104.19) v2(47.85,26.67) v2(47.93,110.74) v2(48.08,116.05) v2(48.26,132.72) v2(48.26,0.64) v2(48.31,81.81) v2(48.31,79.38) v2(48.41,112.14) v2(48.41,109.14) v2(48.62,84.12) v2(48.67,74.35) v2(48.68,123.49) v2(48.87,75.56) v2(48.95,114.53) v2(48.95,77.17) v2(48.97,105.74) v2(49.11,94.14) v2(49.2,91.9) v2(49.45,82.93) v2(49.5,122.67) v2(49.56,116.76) v2(49.61,79.91) v2(49.76,10.16) v2(49.76,6.35) v2(50.17,139.06) v2(50.15,124.41) v2(50.11,104.14) v2(50.14,101.85) v2(50.19,3.07) v2(50.29,110.74) v2(50.54,121.65) v2(50.5,90.47) v2(50.5,84.15) v2(50.57,115.8) v2(50.8,128.27) v2(50.8,46.99) v2(50.8,36.83) v2(51.04,123.45) v2(50.98,20.83) v2(51.03,19.05) v2(51.03,13.97) v2(51.13,79.91) v2(51.16,73.23) v2(51.26,105.79) v2(51.18,29.41) v2(51.41,70.59) v2(51.49,102.95) v2(51.76,120.44) v2(51.69,92.23) v2(51.89,122.68) v2(51.94,89.76) v2(51.97,83.06) v2(51.99,87.58) v2(51.99,85.24) v2(52.07,132.72) v2(52.07,99.8) v2(52.22,79.63) v2(52.69,119.63) v2(52.68,104.14) v2(52.84,121.61) v2(52.81,81.56) v2(52.93,91.52) v2(53.11,80.54) v2(53.09,73.48) v2(53.11,59.46) v2(53.37,93.57) v2(53.34,52.07) v2(53.34,41.91) v2(53.34,0.64) v2(53.49,101.42) v2(53.6,119.05) v2(53.59,76.43) v2(53.67,121.92) v2(53.82,114.71) v2(53.92,84.3) v2(53.98,139.06) v2(54.05,109.65) v2(54.23,90.14) v2(54.23,58.34) v2(54.23,24.23) v2(54.2,15.88) v2(54.2,9.53) v2(54.36,106.63) v2(54.33,82.68) v2(54.31,80.62) v2(54.41,110.92) v2(54.48,79.17) v2(54.56,60.43) v2(54.61,77.6) v2(54.81,107.98) v2(54.79,104.72) v2(54.81,93.62) v2(54.86,92.18) v2(54.84,12.7) v2(55.07,61.42) v2(55.17,3.02) v2(55.25,102.23) v2(55.19,27.36) v2(55.32,121.98) v2(55.35,118.36) v2(55.35,116.59) v2(55.32,75.74) v2(55.45,120.4) v2(55.37,84.05) v2(55.4,72.21) v2(55.45,69.19) v2(55.42,65.99) v2(55.52,81.89) v2(55.58,80.39) v2(55.63,79.02) v2(55.6,59.36) v2(55.7,56.87) v2(55.8,108.03) v2(55.88,128.27) v2(55.88,46.99) v2(55.88,36.83) v2(56.08,60.43) v2(56.18,106.07) v2(56.29,73.05) v2(56.44,61.57) v2(56.52,65.33) v2(56.59,69.55) v2(56.77,104.32) v2(56.72,92.86) v2(56.72,90.14) v2(56.74,24.76) v2(56.9,100.69) v2(56.9,58.06) v2(57.02,82.93) v2(57.02,81.28) v2(57,79.88) v2(57.15,139.06) v2(57.15,84.05) v2(57.15,77.6) v2(57.23,55.3) v2(57.35,74.14) v2(57.33,60.6) v2(57.3,59.18) v2(57.3,0.71) v2(57.48,64.34) v2(57.63,70.56) v2(57.71,107.75) v2(58.01,9.53) v2(58.17,102.9) v2(58.14,80.87) v2(58.24,56.72) v2(58.39,75.18) v2(58.42,41.91) v2(58.57,122) v2(58.6,109.17) v2(58.62,91.19) v2(58.65,17.14) v2(58.65,13.97) v2(58.75,94.89) v2(58.67,59.11) v2(58.72,53.82) v2(58.85,107.72) v2(58.8,99.36) v2(59.06,84.07) v2(59.06,81.92) v2(59.06,72.01) v2(59.36,87.83) v2(59.31,75.87) v2(59.28,22.86) v2(59.28,19.05) v2(59.44,105.59) v2(59.69,52.45) v2(59.69,50.6) v2(59.69,48.26) v2(59.84,56.87) v2(59.82,55.12) v2(59.92,5.71) v2(60.05,92.68) v2(59.99,72.95) v2(60.1,58.52) v2(60.17,61.7) v2(60.3,76.53) v2(60.35,45.95) v2(60.66,89.08) v2(60.68,17.65) v2(60.68,16.89) v2(60.68,16.13) v2(60.86,99.92) v2(60.81,96.88) v2(60.81,86.77) v2(60.81,85.19) v2(60.83,83.44) v2(60.78,60.3) v2(60.96,90.17) v2(60.96,73.86) v2(60.96,36.83) v2(60.96,0.64) v2(61.19,24.13) v2(61.37,53.34) v2(61.37,51.64) v2(61.37,49.63) v2(61.44,17.65) v2(61.44,16.89) v2(61.44,16.13) v2(61.49,75.51) v2(61.59,139.06) v2(61.65,47.55) v2(61.67,101.45) v2(61.72,77.24) v2(61.7,57.68) v2(61.85,94.41) v2(62.03,105.41) v2(62.2,98.32) v2(62.33,88.24) v2(62.36,44.88) v2(62.28,14.05) v2(62.43,89.99) v2(62.69,59.46) v2(62.79,85.78) v2(62.97,17.65) v2(62.97,16.89) v2(62.97,16.13) v2(62.97,3.66) v2(62.99,115.09) v2(63.07,77.22) v2(63.12,75.54) v2(63.32,125.91) v2(63.32,101.7) v2(63.32,99.82) v2(63.35,57.68) v2(63.35,46.58) v2(63.5,128.27) v2(63.55,105.26) v2(63.5,67.31) v2(63.5,52.07) v2(63.5,41.91) v2(63.5,31.75) v2(63.73,17.65) v2(63.73,16.89) v2(63.73,16.13) v2(63.8,96.34) v2(64.36,27.3) v2(64.41,115.09) v2(64.62,8.59) v2(64.77,132.72) v2(64.77,0.64) v2(64.92,126.19) v2(65.15,114.38) v2(65.43,97.99) v2(65.63,13.97) v2(65.76,137.95) v2(65.84,135.69) v2(65.81,123.72) v2(65.86,105.59) v2(65.84,101.73) v2(65.81,99.95) v2(65.94,44.3) v2(66.04,95.25) v2(66.04,80.01) v2(66.04,72.39) v2(66.04,62.23) v2(66.04,36.83) v2(66.12,127.36) v2(66.09,47.17) v2(66.5,130.66) v2(66.75,136.78) v2(66.75,134.62) v2(66.68,90.6) v2(66.78,139.06) v2(66.85,77.93) v2(66.83,74.83) v2(66.83,59.99) v2(66.83,57.12) v2(66.9,17.78) v2(66.9,8.89) v2(67.06,106.4) v2(67.03,104.09) v2(67.11,128.35) v2(67.16,125.09) v2(67.16,3.68) v2(67.39,12.19) v2(67.51,87.76) v2(67.97,139.06) v2(68.1,122.15) v2(68.12,44.3) v2(68.17,47.14) v2(68.35,131.78) v2(68.61,126.52) v2(68.58,102.87) v2(68.58,52.07) v2(68.58,41.91) v2(68.58,31.75) v2(68.58,0.64) v2(69.06,82.63) v2(69.39,8.43) v2(69.85,92.71) v2(70.03,127.97) v2(70.15,133.07) v2(70.38,131.37) v2(70.46,129.67) v2(70.64,139.04) v2(70.71,17.78) v2(71.02,44.32) v2(71.12,105.41) v2(71.12,100.33) v2(71.12,85.09) v2(71.12,80.01) v2(71.12,64.77) v2(71.09,47.14) v2(71.12,36.83) v2(71.09,3.86) v2(71.35,26.67) v2(71.35,22.86) v2(71.93,139.04) v2(71.93,136.88) v2(71.91,134.59) v2(72.62,13.34) v2(72.85,137.97) v2(72.92,135.71) v2(73.03,0.64) v2(73.43,87.38) v2(73.48,47.8) v2(73.51,43.54) v2(73.66,120.65) v2(73.66,109.86) v2(73.66,96.52) v2(73.66,69.85) v2(73.66,52.07) v2(73.66,41.91) v2(73.66,31.75) v2(73.86,56.11) v2(74.04,61.04) v2(74.52,17.78) v2(74.85,78.74) v2(74.98,73.89) v2(75.34,6.58) v2(75.41,86.69) v2(75.62,43.28) v2(75.9,56.01) v2(76.12,91.57) v2(76.1,48.11) v2(76.2,139.06) v2(76.2,133.35) v2(76.2,115.57) v2(76.2,105.41) v2(76.2,82.55) v2(76.2,64.77) v2(76.2,36.83) v2(76.43,8.89) v2(76.66,11.66) v2(76.89,61.01) v2(76.99,73.89) v2(77.37,110.62) v2(77.47,113.67) v2(77.8,43.28) v2(77.95,78.74) v2(77.98,4.5) v2(78.11,100.97) v2(78.11,56.01) v2(78.28,86.84) v2(78.33,17.78) v2(78.36,0.38) v2(78.41,97.54) v2(78.61,91.49) v2(78.61,48.03) v2(78.74,120.65) v2(78.77,89.1) v2(78.71,76.33) v2(78.74,69.85) v2(78.69,58.47) v2(78.74,52.07) v2(78.74,31.75) v2(79.07,45.72) v2(79.2,73.3) v2(79.2,61.29) v2(79.22,54.91) v2(79.58,85.32) v2(79.6,41.88) v2(80.01,139.06) v2(80.14,49.5) v2(80.19,80.9) v2(80.54,92.94) v2(80.65,3.81) v2(80.87,3.81) v2(81.28,111.76) v2(81.28,105.41) v2(81.28,95.25) v2(81.28,36.83) v2(81.51,6.71) v2(82.04,80.01) v2(82.04,72.36) v2(81.99,62.1) v2(82.02,54.48) v2(82.25,85.37) v2(82.22,49.56) v2(82.32,41.91) v2(82.6,101.73) v2(82.78,12.7) v2(82.78,9.53) v2(83.16,83.9) v2(83.52,91.39) v2(83.57,89.23) v2(83.57,86.97) v2(83.54,78.28) v2(83.52,73.91) v2(83.57,56.06) v2(83.59,76.15) v2(83.59,60.45) v2(83.59,58.32) v2(83.69,48.01) v2(83.69,45.69) v2(83.72,43.54) v2(83.82,133.35) v2(83.82,120.65) v2(83.82,69.85) v2(83.82,64.77) v2(83.82,52.07) v2(83.82,31.75) v2(83.82,21.59) v2(83.82,11.43) v2(83.82,0.64) v2(84.46,139.06) v2(84.46,117.48) v2(84.46,3.81) v2(85.04,92.94) v2(84.99,62.1) v2(85.17,41.91) v2(85.5,79.96) v2(85.57,54.43) v2(85.9,72.36) v2(86,49.53) v2(86.36,136.53) v2(86.36,100.33) v2(86.36,95.25) v2(86.36,82.55) v2(86.36,36.83) v2(86.36,26.67) v2(86.36,16.51) v2(86.36,6.35) v2(87.02,105.03) v2(87.17,85.29) v2(87.63,108.59) v2(87.63,0.64) v2(87.86,92.51) v2(87.88,61.62) v2(87.88,41.91) v2(88.29,72.85) v2(88.54,79.5) v2(88.65,44.02) v2(88.77,54.97) v2(88.9,139.06) v2(88.9,133.35) v2(88.9,118.11) v2(88.9,84.33) v2(88.95,77.9) v2(88.9,69.85) v2(88.9,64.77) v2(88.9,52.07) v2(88.93,49.05) v2(88.9,31.75) v2(88.9,21.59) v2(88.9,11.43) v2(89.2,60.02) v2(89.48,74.45) v2(89.64,47.4) v2(89.76,56.57) v2(89.87,85.83) v2(89.94,92.99) v2(90.02,90.53) v2(90.02,42.11) v2(90.27,70.76) v2(90.35,38.2) v2(90.4,97.38) v2(90.4,95.05) v2(90.4,64.74) v2(90.4,62.28) v2(90.37,40.16) v2(90.5,80.9) v2(90.65,50.29) v2(90.68,53.8) v2(90.93,129.16) v2(90.91,68.43) v2(91.24,36.35) v2(91.44,100.33) v2(91.44,82.55) v2(91.44,26.67) v2(91.44,16.51) v2(91.44,6.35) v2(92.2,99.34) v2(92.2,66.45) v2(92.41,84.56) v2(92.63,70.18) v2(92.71,139.06) v2(92.71,123.19) v2(92.76,63.98) v2(92.68,41.76) v2(92.74,39.73) v2(92.79,96.85) v2(92.79,72.21) v2(93.17,81.05) v2(93.19,38.07) v2(93.32,91.82) v2(93.52,43.38) v2(93.73,50.44) v2(93.7,41.05) v2(93.68,35.71) v2(93.85,67.69) v2(93.93,86.49) v2(93.98,79.15) v2(94.03,56.06) v2(94.01,53.64) v2(93.98,52.07) v2(93.98,31.75) v2(93.98,21.59) v2(93.98,11.43) v2(93.98,0.64) v2(94.18,48.84) v2(94.41,129.21) v2(94.62,117.07) v2(94.62,99.36) v2(94.82,66.47) v2(94.84,39.24) v2(95.02,92.43) v2(95.1,84.56) v2(95.15,74.32) v2(95.12,72.39) v2(95.1,62.08) v2(95.15,59.49) v2(95.3,43.74) v2(95.38,94.08) v2(95.61,35.66) v2(96.14,81.03) v2(96.52,139.06) v2(96.52,82.55) v2(96.52,26.67) v2(96.52,16.51) v2(96.52,6.35) v2(96.7,50.57) v2(96.72,39.24) v2(97.08,108.69) v2(97.08,70.71) v2(97.21,53.59) v2(97.51,95.83) v2(97.89,85.06) v2(98.4,87.99) v2(98.53,75.49) v2(98.5,57.15) v2(98.76,47.04) v2(98.73,39.19) v2(98.86,107.75) v2(98.86,54.71) v2(98.78,49.43) v2(98.93,61.98) v2(99.06,52.07) v2(99.06,31.75) v2(99.06,21.59) v2(99.06,11.43) v2(99.06,0.64) v2(99.09,70.71) v2(99.14,67.69) v2(99.19,35.71) v2(99.29,80.01) v2(99.31,66.47) v2(99.57,139.06) v2(99.52,95.89) v2(99.9,92.68) v2(100.13,57.05) v2(100.23,77.67) v2(100.33,113.89) v2(100.3,85.52) v2(100.51,64.11) v2(100.51,38.05) v2(100.63,49.43) v2(100.74,99.34) v2(101.07,54.71) v2(101.17,87.93) v2(101.3,67.67) v2(101.32,47.07) v2(101.6,96.98) v2(101.6,82.55) v2(101.6,26.67) v2(101.6,16.51) v2(101.6,6.35) v2(101.73,35.69) v2(101.9,66.47) v2(102.03,80.04) v2(102.49,139.06) v2(102.67,69.8) v2(102.72,85.55) v2(102.87,0.64) v2(103,49.43) v2(103.33,96.37) v2(103.28,38.13) v2(103.5,99.34) v2(103.76,107.7) v2(103.89,67.46) v2(103.96,54.66) v2(104.01,87.93) v2(104.04,35.69) v2(104.14,52.07) v2(104.17,47.09) v2(104.14,31.75) v2(104.14,21.59) v2(104.14,11.43) v2(104.42,126.44) v2(104.5,77.7) v2(104.72,66.01) v2(104.67,57.02) v2(104.83,80.04) v2(105.41,114.53) v2(105.49,97.87) v2(105.61,85.57) v2(105.64,68.99) v2(105.69,70.71) v2(105.69,64.24) v2(105.71,49.43) v2(105.71,37.67) v2(105.79,139.06) v2(105.79,112.52) v2(106.68,136.53) v2(106.68,130.81) v2(106.68,120.24) v2(106.68,108.81) v2(106.68,82.55) v2(106.68,54.69) v2(106.68,36.83) v2(106.68,26.67) v2(106.68,16.51) v2(106.68,6.35) v2(106.68,0.64) v2(106.83,87.96) v2(107.14,47.04) v2(107.67,80.04) v2(107.95,117.7) v2(108.33,49.43) v2(108.74,85.52) v2(109.12,77.11) v2(109.22,100.33) v2(109.22,64.77) v2(109.22,52.07) v2(109.22,41.91) v2(109.22,31.75) v2(109.22,21.59) v2(109.22,11.43) v2(109.27,57.05) v2(109.47,88.32) v2(109.6,54.66) v2(109.58,46.61) v2(110.08,79.53) v2(110.24,139.06) v2(110.49,0.64) v2(110.79,75.41) v2(110.92,48.54) v2(111.05,86.54) v2(111,58.8) v2(111.12,89.97) v2(111.15,44.98) v2(111.4,55.91) v2(111.76,133.35) v2(111.76,95.25) v2(111.76,82.55) v2(111.68,77.9) v2(111.76,69.85) v2(111.76,36.83) v2(111.76,26.67) v2(111.76,16.51) v2(111.76,6.35) v2(112.4,122.78) v2(112.57,87.99) v2(112.75,46.76) v2(112.98,75.21) v2(113,44.32) v2(113.16,139.06) v2(113.36,59.44) v2(113.28,57.1) v2(114.3,100.33) v2(114.3,64.77) v2(114.3,52.07) v2(114.3,31.75) v2(114.3,21.59) v2(114.3,11.43) v2(114.3,0.64) v2(116.21,139.06) v2(116.21,111.76) v2(116.21,6.35) v2(116.84,133.35) v2(116.84,128.27) v2(116.84,95.25) v2(116.84,82.55) v2(116.84,69.85) v2(116.84,36.83) v2(116.84,26.67) v2(116.84,16.51) v2(116.84,6.35) v2(119.38,100.33) v2(119.38,64.77) v2(119.38,52.07) v2(119.38,31.75) v2(119.38,21.59) v2(119.38,11.43) v2(120.02,111.76) v2(120.27,108.94) v2(120.27,108.18) v2(120.27,107.42) v2(120.27,106.65) v2(120.27,105.89) v2(120.65,139.06) v2(121.11,108.94) v2(121.11,108.18) v2(121.11,107.42) v2(121.11,106.65) v2(121.11,105.89) v2(121.92,108.94) v2(121.92,108.18) v2(121.92,107.42) v2(121.92,106.65) v2(121.92,105.89) v2(122.56,137.8) v2(122.56,133.99) v2(122.56,130.17) v2(122.56,126.37) v2(122.56,122.56) v2(122.56,121.31) v2(122.56,118.75) v2(122.56,116.84) v2(122.56,113.03) v2(122.56,109.98) v2(122.56,104.9) v2(122.56,101.6) v2(122.56,97.79) v2(122.56,93.98) v2(122.56,90.17) v2(122.56,86.36) v2(122.56,82.55) v2(122.56,78.74) v2(122.56,74.93) v2(122.56,71.12) v2(122.56,67.31) v2(122.56,63.5) v2(122.56,59.69) v2(122.56,55.88) v2(122.56,52.07) v2(122.56,48.26) v2(122.56,44.45) v2(122.56,40.64) v2(122.56,36.83) v2(122.56,33.02) v2(122.56,29.21) v2(122.56,25.4) v2(122.56,21.59) v2(122.56,17.78) v2(122.56,13.97) v2(122.56,10.16) v2(122.56,6.35) v3(32.34,110.35) v3(32.34,108.35) v3(32.45,117.97) v3(32.45,115.97) v3(32.42,102.8) v3(32.42,100.8) v3(32.6,125.76) v3(32.6,123.76) v3(33.24,111.45) v3(33.24,107.25) v3(33.35,119.07) v3(33.35,114.87) v3(33.32,103.9) v3(33.32,99.7) v3(33.28,91.72) v3(33.42,93.14) v3(33.5,126.86) v3(33.5,122.66) v3(34.76,90.1) v3(34.83,94.55) v3(35.44,111.55) v3(35.44,107.15) v3(35.55,119.17) v3(35.55,114.77) v3(35.52,104) v3(35.52,99.6) v3(35.7,126.96) v3(35.7,122.56) v3(35.82,89.46) v3(36.25,94.69) v3(36.64,111.25) v3(36.64,107.45) v3(36.75,118.87) v3(36.75,115.07) v3(36.72,103.7) v3(36.72,99.9) v3(36.9,126.66) v3(36.9,122.86) v3(37.87,93.21) v3(38.31,132.78) v3(38.41,134.98) v3(38.51,92.15) v3(38.61,131.58) v3(39.51,135.88) v3(41.51,135.88) v3(42.41,131.58) v3(42.61,134.98) v3(42.71,132.78) v3(45.65,86.35) v3(45.75,88.55) v3(45.95,85.15) v3(46.85,89.45) v3(48.85,89.45) v3(49.75,85.15) v3(49.95,88.55) v3(50.05,86.35) v3(53.63,95.92) v3(53.73,98.12) v3(53.93,94.72) v3(54.04,86.35) v3(54.14,88.55) v3(54.34,85.15) v3(54.83,99.02) v3(55.24,89.45) v3(56.83,99.02) v3(57.24,89.45) v3(57.73,94.72) v3(57.93,98.12) v3(58.03,95.92) v3(58.14,85.15) v3(58.34,88.55) v3(58.44,86.35) v4(46.34,97.12) v4(46.34,96.05) v4(46.88,96.58) v4(47.42,97.12) v4(47.42,96.05) v5(61.43,114.46) v5(61.42,114.45) v5(61.43,113.44) v5(62.45,113.44) v5(62.45,112.42) v5(63.47,114.46) v5(63.47,113.44) v5(63.47,112.42) v5(63.47,111.41) v5(64.48,114.46) v5(64.48,113.44) v5(64.48,112.42)
VCC: length 136.8
  TOP w0.305: v2(17.48,107.31) 17.77,107.02 U15.5 ; U11.7 56.4,19.95 56.42,19.96 57.12,19.96 57.13,19.95 57.25,19.95 57.51,19.69 v2(57.51,19.68) ; U11.2 52.66,20.95 v2(52.53,21.08) ; v2(57.12,21.08) 56.99,20.95 U11.9 ; U15.8 v2(17.43,105.07) ; U15.7 v2(17.44,105.72) ; U11.3 v2(52.55,20.45)
  TOP w0.508: C237.1 v2(51.79,22.1) ; v2(16.99,102.62) C117.1 v2(17.7,103.28) ; 17.6,100.58 v2(16.84,100.58) ; 17.6,100.58 v2(17.6,100.15) ; 17.6,100.58 C135.1 ; C112.1 v2(50.77,22.1) ; C161.1 v2(48.11,22.1) ; C111.1 v2(49.63,22.1)
  L3_PWR w2.032: 34.29,26.04 32.36,27.97 32.36,39.65 27.53,44.48 5.05,44.48 4.57,44.96 4.5,44.96 3.68,45.78 3.68,45.85 3.18,46.36 3.18,90.93 8.48,96.24 13,96.24 17.7,100.94 v2(17.7,103.28)
  BOTTOM w0.508: C155.1 v2(46.58,23.62) ; v2(46.08,25.65) 45.95,25.65 45.19,24.89 FB20.1 ; FB20.1 v2(46.08,24.76) ; FB20.1 v2(46.08,23.88) ; C154.1 v2(45.57,23.62) ; R143.2 v2(45.57,26.54)
  BOTTOM w1.016: v2(17.48,107.31) 17.48,105.75 v2(17.44,105.72) 17.44,105.08 v2(17.43,105.07) 17.7,104.8 v2(17.7,103.28) 17.65,103.28 v2(16.99,102.62) 16.84,102.46 v2(16.84,100.58) 17.17,100.58 v2(17.6,100.15)
VCC_AUXIN: length 3.8
  TOP w0.305: C58.1 v2(62.39,118.13) 62.43,118.08 62.43,117.5 62.21,117.27 U2.44
  BOTTOM w0.508: FB3.2 61.98,118.54 v2(62.39,118.13) 62.39,117.64 C61.1
VCC_PLL: length 8.1
  TOP w0.305: C57.1 v2(64.8,118.08) ; U2.39 v2(64.71,117.29) ; U2.42 63.21,117.46 v2(63.22,117.48) ; v2(63.22,118.14) C56.1
  BOTTOM w0.305: 64.8,117.37 v2(64.71,117.29)
  BOTTOM w0.508: FB4.2 65.33,118.31 v2(65.53,118.11) C60.1 65.52,117.29 v2(64.71,117.29) 64.7,117.3 C59.1 63.4,117.3 v2(63.22,117.48) v2(63.22,118.14) ; v2(64.8,118.08) 64.8,117.37
VCC_VCO: length 7.1
  TOP w0.305: C69.1 v2(68.1,115.34) 67.61,115.34 v2(67.46,115.18) U2.35 ; C70.1 v2(68.15,114.58) 68.02,114.45 v2(67.46,114.45) 67.23,114.68 U2.34
  BOTTOM w0.508: C72.1 v2(68.3,117.42) ; v2(67.46,114.45) 67.39,114.53 66.17,114.53 C71.1 ; FB7.2 v2(67.59,116.28)
VDD1: length 4.3
  TOP w0.305: v2(44.25,95.05) 44.85,95.65 U6.14 ; U6.17 45.92,94.59 v2(45.26,93.93)
  TOP w0.508: C101.1 43.03,94.9 v2(43.38,94.54) ; C90.1 v2(44.83,93.06)
  BOTTOM w0.508: v2(43.71,95.2) 43.57,95.34 43.57,95.76 C62.1 ; FB15.1 45.91,93.06 v2(45.68,93.3)
A1OUT: length 27.5
  TOP w0.305: J8.1 104.52,97.16 103.5,98.17 99.99,98.17 99.72,97.9 99.72,97.3 99.45,97.03 99.07,97.03 98.8,97.3 98.8,97.9 98.54,98.17 98.16,98.17 97.89,97.9 97.89,97.3 97.62,97.03 97.24,97.03 96.97,97.3 96.97,97.9 96.71,98.17 96.33,98.17 96.06,97.9 96.06,97.3 95.79,97.03 95.41,97.03 95.15,97.3 95.15,97.9 94.88,98.17 92.46,98.17 91.57,97.28 R42.2
A2OUT: length 20.9
  TOP w0.305: T4.1 109.58,86.74 111.99,89.15 J7.1
ALARM: length 77.1
  BOTTOM w0.102: U1.N12 48.94,63.09 49.28,63.42 51,63.42
  BOTTOM w0.152: TP5.1 94.18,113.44 94.18,104.75 92.99,103.56 86.18,103.56 77.22,94.59 76.33,94.59 75.11,93.37 75.11,92.2 72.54,89.64 71.25,89.64 54.31,72.69 54.31,64.92 52.81,63.42 51,63.42
B1OUT: length 27.5
  TOP w0.305: R28.2 91.44,69.57 92.35,68.66 93.07,68.66 93.34,68.92 93.34,69.3 93.6,69.57 93.98,69.57 94.25,69.3 94.25,68.92 94.52,68.66 94.9,68.66 95.17,68.92 95.17,69.3 95.43,69.57 95.81,69.57 96.08,69.3 96.08,68.92 96.35,68.66 96.73,68.66 96.99,68.92 96.99,69.3 97.26,69.57 97.64,69.57 97.91,69.3 97.91,68.92 98.18,68.66 98.56,68.66 98.82,68.92 98.82,69.3 99.09,69.57 99.47,69.57 99.74,69.3 99.74,68.92 100.01,68.66 100.38,68.66 100.65,68.92 100.65,69.3 100.92,69.57 101.3,69.57 101.57,69.3 101.57,68.92 101.83,68.66 103.63,68.66 104.52,69.55 J5.1
B2OUT: length 21
  TOP w0.305: J6.1 116.89,76.38 111.53,76.38 109.04,78.87 T3.3
C1OUT: length 27.4
  TOP w0.305: J4.1 104.5,60.35 104.5,64.57 103.89,65.18 99.15,65.18 98.88,64.91 98.88,63.89 98.62,63.63 98.24,63.63 97.97,63.89 97.97,64.91 97.7,65.18 97.32,65.18 97.05,64.91 97.05,63.89 96.79,63.63 96.41,63.63 96.14,63.89 96.14,64.91 95.87,65.18 95.49,65.18 95.23,64.91 95.23,63.89 94.96,63.63 94.58,63.63 94.31,63.89 94.31,64.91 94.04,65.18 92.05,65.18 91.57,64.69 R25.2
C2OUT: length 20.8
  TOP w0.305: J3.1 112.19,58.29 109.78,55.88 T2.1
CDC-PRIREF+: length 19.2
  TOP w0.305: C53.2 R47.2 R50.1 69.29,128.88 65.15,124.74 63.35,124.74 61.26,122.66 61.26,118.11 61.71,117.67 U2.45
CDC-PRIREF-: length 12.3
  TOP w0.152: U2.46 61.21,117.25 60.4,118.06 60.4,118.35 60.3,118.45 60.3,126.7 JP4.2
CDC_READ: length 3.1
  BOTTOM w0.152: R78.2 102.3,113.53 U3.11
CDCOUT: length 3.1
  TOP w0.305: R88.2 50.32,113.69 R56.1 R53.2 R54.1
CDCOUT\: length 4
  TOP w0.305: R120.2 49.88,112.64 R59.1 R57.2 52.39,112.68 R58.1
D1OUT: length 27.5
  TOP w0.305: R4.2 91.57,37.69 92.38,36.88 94.12,36.88 94.39,37.15 94.39,37.78 94.66,38.05 95.04,38.05 95.3,37.78 95.3,37.15 95.57,36.88 95.95,36.88 96.22,37.15 96.22,37.78 96.49,38.05 96.86,38.05 97.13,37.78 97.13,37.15 97.4,36.88 97.78,36.88 98.05,37.15 98.05,37.78 98.31,38.05 98.69,38.05 98.96,37.78 98.96,37.15 99.23,36.88 103.68,36.88 104.57,37.77 104.57,42.24 J1.1
D2OUT: length 20.9
  TOP w0.305: T1.3 109.55,48.26 112.24,45.57 116.94,45.57 J2.1
DA0N: length 66.9
  TOP w0.127: v2(9.32,52.6) 8.97,52.6 8.61,52.25 8.61,51.69 10.44,49.86 10.9,49.86 12.73,48.03 23.22,48.03 24.7,49.51 25.53,49.51 25.66,49.64 25.66,49.82 25.11,50.37 25.11,50.76 25.38,51.03 25.77,51.03 26.32,50.48 26.5,50.48 26.63,50.61 26.63,50.79 26.08,51.34 26.08,51.73 26.35,52 26.74,52 27.29,51.45 27.47,51.45 27.6,51.58 27.6,51.76 27.05,52.31 27.05,52.7 27.32,52.97 27.71,52.97 28.26,52.42 28.44,52.42 28.57,52.55 28.57,52.73 28.02,53.28 28.02,53.67 28.29,53.94 28.68,53.94 29.23,53.39 29.41,53.39 29.54,53.52 29.54,53.7 28.99,54.25 28.99,54.64 29.26,54.91 29.65,54.91 30.2,54.36 30.38,54.36 30.51,54.49 30.51,54.67 29.96,55.22 29.96,55.61 30.23,55.88 30.62,55.88 31.17,55.33 31.35,55.33 31.48,55.46 31.48,55.64 30.93,56.19 30.93,56.58 31.2,56.85 31.59,56.85 32.14,56.3 32.32,56.3 32.45,56.43 32.45,56.61 31.9,57.16 31.9,57.55 32.17,57.82 32.56,57.82 33.11,57.27 33.29,57.27 33.42,57.4 33.42,57.58 32.87,58.13 32.87,58.52 33.14,58.79 33.53,58.79 34.08,58.24 34.26,58.24 34.39,58.37 34.39,58.55 33.84,59.1 33.84,59.49 34.11,59.76 34.5,59.76 35.05,59.21 35.23,59.21 35.36,59.34 35.36,59.52 35.23,59.65 35.23,60.04 38.3,63.12 38.3,64.57 39.75,66.01 39.75,66.4 39.98,66.63 41.09,66.63 41.33,66.87 41.33,67.19 41.74,67.59 U1.G3
  BOTTOM w0.152: J13.165 7.71,52.51 7.77,52.58 8.5,52.58 8.54,52.53 9.25,52.53 v2(9.32,52.6)
DA0P: length 67.6
  TOP w0.127: v2(8.74,53.01) 8.74,52.76 8.36,52.37 8.36,51.59 10.34,49.61 10.8,49.61 12.62,47.78 23.32,47.78 24.8,49.26 25.63,49.26 25.91,49.53 25.91,49.92 25.36,50.47 25.36,50.65 25.49,50.78 25.66,50.78 26.22,50.23 26.6,50.23 26.88,50.5 26.88,50.89 26.33,51.44 26.33,51.62 26.46,51.75 26.64,51.75 27.19,51.2 27.58,51.2 27.85,51.47 27.85,51.86 27.3,52.41 27.3,52.59 27.43,52.72 27.61,52.72 28.16,52.17 28.55,52.17 28.82,52.44 28.82,52.83 28.27,53.38 28.27,53.56 28.4,53.69 28.58,53.69 29.13,53.14 29.52,53.14 29.79,53.41 29.79,53.8 29.24,54.35 29.24,54.53 29.37,54.66 29.55,54.66 30.1,54.11 30.49,54.11 30.76,54.38 30.76,54.77 30.21,55.32 30.21,55.5 30.34,55.63 30.52,55.63 31.07,55.08 31.46,55.08 31.73,55.35 31.73,55.74 31.18,56.29 31.18,56.47 31.31,56.6 31.49,56.6 32.04,56.05 32.43,56.05 32.7,56.32 32.7,56.71 32.15,57.26 32.15,57.44 32.28,57.57 32.46,57.57 33.01,57.02 33.4,57.02 33.67,57.29 33.67,57.68 33.12,58.23 33.12,58.41 33.25,58.54 33.43,58.54 33.98,57.99 34.37,57.99 34.64,58.26 34.64,58.65 34.09,59.2 34.09,59.38 34.22,59.51 34.4,59.51 34.95,58.96 35.34,58.96 35.61,59.24 35.61,59.62 35.48,59.76 35.48,59.94 38.56,63.01 38.56,64.46 39.94,65.84 41.1,65.84 41.35,66.09 41.35,66.4 41.58,66.63 41.89,66.63 42.13,66.87 42.13,67.41 42.54,67.81 U1.G4
  BOTTOM w0.152: v2(8.74,53.01) 8.66,52.93 7.79,52.93 7.71,53.01 J13.163
